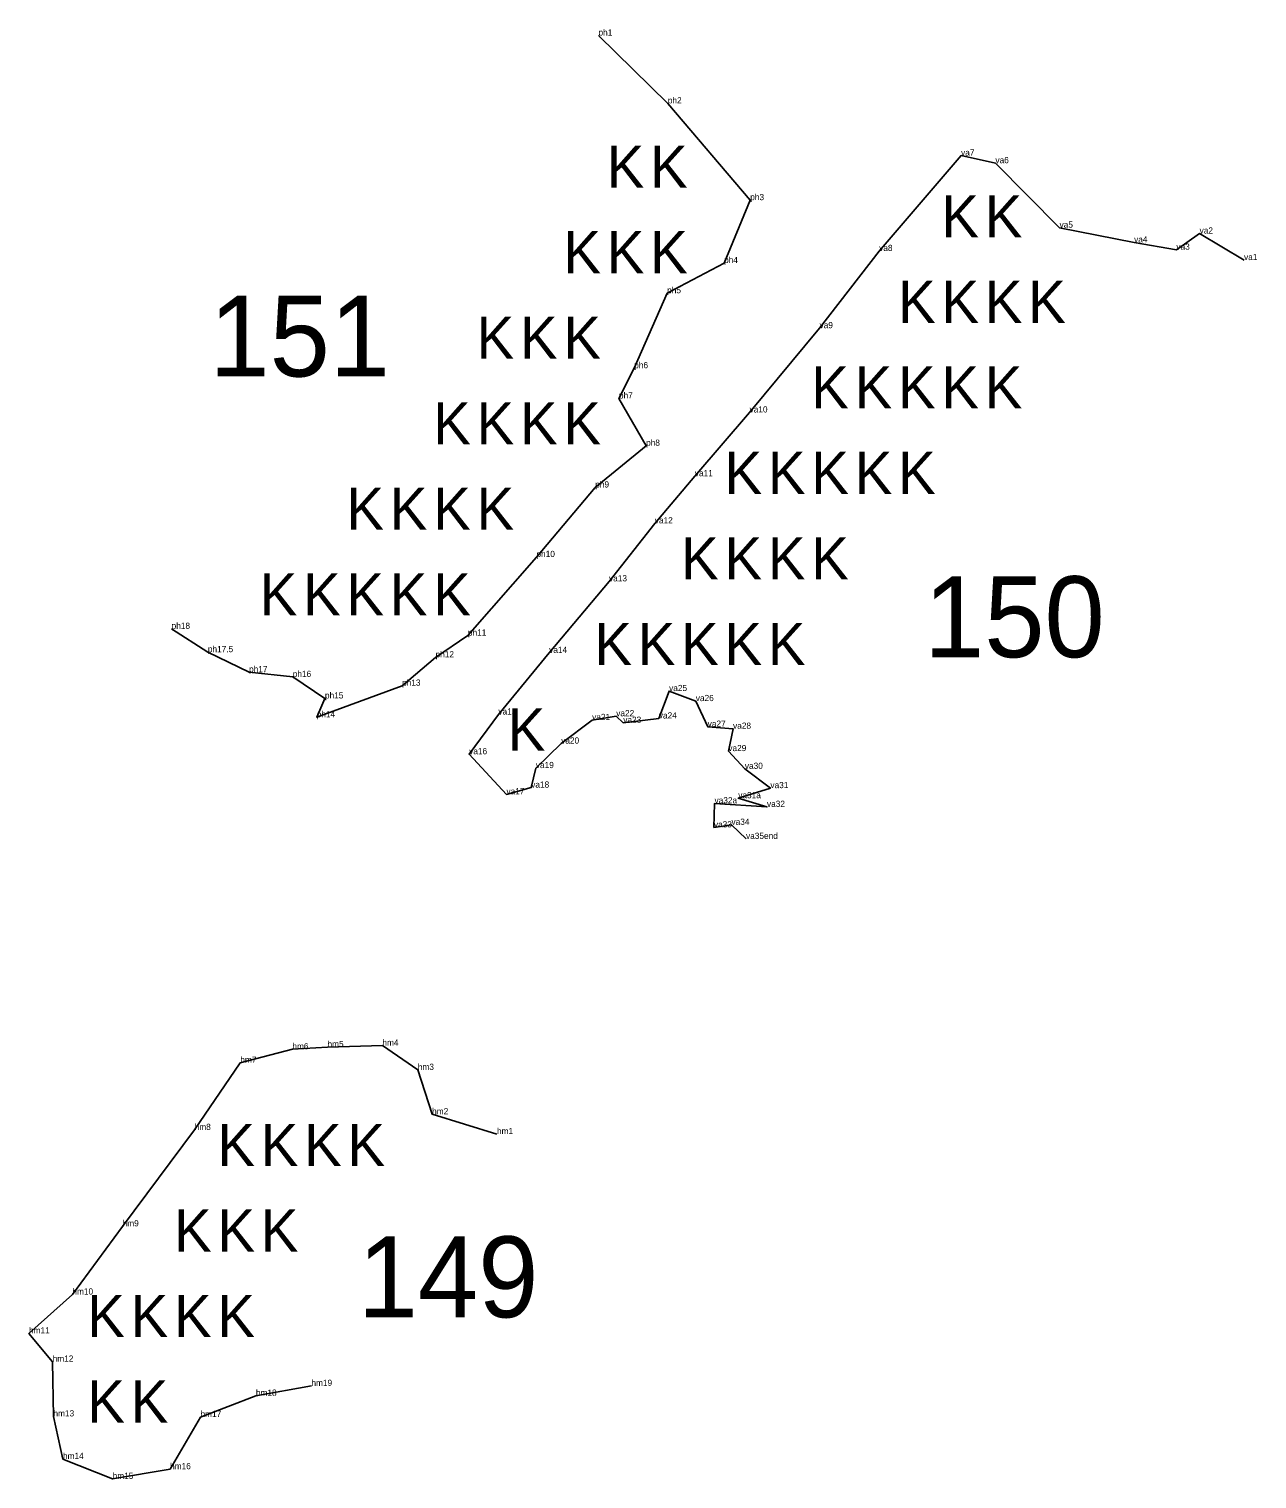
# Model space of a CAD drawing. Extents: x 2072529 to 2268812, y 436423 to 470008.
# Drawn here: x 2173124 to 2174115, y 447172 to 448342 of the extents above; entities that cross this region are included whole.
import ezdxf

# ---------------------------------------------------------------- set-up
doc = ezdxf.new("R2010")
doc.units = 0
for name, color, linetype in [('Old_Level_20', 7, 'Continuous'), ('Old_Level_52', 7, 'Continuous'), ('Old_Level_55', 7, 'Continuous'), ('Old_Level_60', 7, 'Continuous'), ('Old_Level_62', 7, 'Continuous')]:
    doc.layers.add(name, color=color, linetype=linetype)

msp = doc.modelspace()

# ---------------------------------------------------------------- linework, layer by layer
at = {"layer": 'Old_Level_20'}
for p, q in [((2173583.466, 448337), (2173583.466, 448337)), ((2173639.399, 448282.22), (2173639.399, 448282.22)), ((2173876.017, 448240.104), (2173876.017, 448240.104)), ((2173903.753, 448233.99), (2173903.753, 448233.99)), ((2173705.912, 448204.16), (2173705.912, 448204.16)), ((2173955.521, 448181.963), (2173955.521, 448181.963)), ((2174015.642, 448170.074), (2174015.642, 448170.074)), ((2174068.516, 448177.248), (2174068.516, 448177.248)), ((2173809.946, 448163.115), (2173809.946, 448163.115)), ((2174049.767, 448164.155), (2174049.767, 448164.155)), ((2174104.347, 448155.801), (2174104.347, 448155.801)), ((2173684.778, 448153.416), (2173684.778, 448153.416)), ((2173638.87, 448129.059), (2173638.87, 448129.059)), ((2173761.851, 448100.844), (2173761.851, 448100.844)), ((2173612.299, 448068.551), (2173612.299, 448068.551)), ((2173599.96, 448044.129), (2173599.96, 448044.129)), ((2173705.376, 448032.846), (2173705.376, 448032.846)), ((2173621.865, 448005.978), (2173621.865, 448005.978)), ((2173661.232, 447981.429), (2173661.232, 447981.429)), ((2173580.838, 447972.298), (2173580.838, 447972.298)), ((2173628.918, 447943.374), (2173628.918, 447943.374)), ((2173533.431, 447916.219), (2173533.431, 447916.219)), ((2173591.986, 447896.56), (2173591.986, 447896.56)), ((2173239.026, 447858.262), (2173239.026, 447858.262)), ((2173478.1, 447852.84), (2173478.1, 447852.84)), ((2173268.278, 447839.435), (2173268.278, 447839.435)), ((2173543.675, 447838.894), (2173543.675, 447838.894)), ((2173452.001, 447835.245), (2173452.001, 447835.245)), ((2173301.538, 447823.257), (2173301.538, 447823.257)), ((2173336.772, 447819.459), (2173336.772, 447819.459)), ((2173425.014, 447812.384), (2173425.014, 447812.384)), ((2173640.445, 447808.038), (2173640.445, 447808.038)), ((2173362.745, 447802.115), (2173362.745, 447802.115)), ((2173661.975, 447799.96), (2173661.975, 447799.96)), ((2173356.081, 447786.898), (2173356.081, 447786.898)), ((2173502.708, 447789.134), (2173502.708, 447789.134)), ((2173578.339, 447784.692), (2173578.339, 447784.692)), ((2173597.789, 447787.733), (2173597.789, 447787.733)), ((2173603.446, 447782.457), (2173603.446, 447782.457)), ((2173632.137, 447785.936), (2173632.137, 447785.936)), ((2173671.593, 447779.273), (2173671.593, 447779.273)), ((2173692.052, 447777.639), (2173692.052, 447777.639)), ((2173479.117, 447757.064), (2173479.117, 447757.064)), ((2173553.392, 447765.678), (2173553.392, 447765.678)), ((2173688.234, 447759.607), (2173688.234, 447759.607)), ((2173532.95, 447745.903), (2173532.95, 447745.903)), ((2173701.582, 447745.298), (2173701.582, 447745.298)), ((2173509.211, 447724.724), (2173509.211, 447724.724)), ((2173529.203, 447730.149), (2173529.203, 447730.149)), ((2173696.239, 447721.595), (2173696.239, 447721.595)), ((2173722.187, 447729.723), (2173722.187, 447729.723)), ((2173677.109, 447717.448), (2173677.109, 447717.448)), ((2173719.425, 447714.583), (2173719.425, 447714.583)), ((2173690.789, 447700.137), (2173690.789, 447700.137)), ((2173676.612, 447698.048), (2173676.612, 447698.048)), ((2173702.522, 447688.766), (2173702.522, 447688.766)), ((2173336.468, 447518.995), (2173336.468, 447518.995)), ((2173364.809, 447520.816), (2173364.809, 447520.816)), ((2173409.121, 447521.961), (2173409.121, 447521.961)), ((2173294.448, 447508.114), (2173294.448, 447508.114)), ((2173437.702, 447502.381), (2173437.702, 447502.381)), ((2173449.257, 447466.546), (2173449.257, 447466.546)), ((2173257.628, 447453.931), (2173257.628, 447453.931)), ((2173501.562, 447450.544), (2173501.562, 447450.544)), ((2173199.479, 447376.158), (2173199.479, 447376.158)), ((2173158.954, 447321.157), (2173158.954, 447321.157)), ((2173123.958, 447289.75), (2173123.958, 447289.75)), ((2173143.038, 447266.952), (2173143.038, 447266.952)), ((2173351.848, 447247.454), (2173351.848, 447247.454)), ((2173307.042, 447239.465), (2173307.042, 447239.465)), ((2173143.681, 447222.783), (2173143.681, 447222.783)), ((2173262.347, 447222.318), (2173262.347, 447222.318)), ((2173151.353, 447188.418), (2173151.353, 447188.418)), ((2173191.46, 447172.374), (2173191.46, 447172.374)), ((2173237.811, 447180.175), (2173237.811, 447180.175))]:
    msp.add_line(p, q, dxfattribs=at)
at = {"layer": 'Old_Level_52'}
for points in [[(2173583.466, 448337), (2173639.399, 448282.22), (2173705.912, 448204.16), (2173684.778, 448153.416), (2173638.87, 448129.059), (2173612.299, 448068.551), (2173599.96, 448044.129), (2173621.865, 448005.978), (2173580.838, 447972.298), (2173533.431, 447916.219), (2173478.1, 447852.84), (2173452.001, 447835.245), (2173425.014, 447812.384), (2173356.081, 447786.898), (2173362.745, 447802.115), (2173336.772, 447819.459), (2173301.538, 447823.257), (2173268.278, 447839.435), (2173239.026, 447858.262)], [(2173702.522, 447688.766), (2173690.789, 447700.137), (2173676.612, 447698.048), (2173677.109, 447717.448), (2173719.425, 447714.583), (2173696.239, 447721.595), (2173722.187, 447729.723), (2173701.582, 447745.298), (2173688.234, 447759.607), (2173692.052, 447777.639), (2173671.593, 447779.273), (2173661.975, 447799.96), (2173640.445, 447808.038), (2173632.137, 447785.936), (2173603.446, 447782.457), (2173597.789, 447787.733), (2173578.339, 447784.692), (2173553.392, 447765.678), (2173532.95, 447745.903), (2173529.203, 447730.149), (2173509.211, 447724.724), (2173479.117, 447757.064), (2173502.708, 447789.134), (2173543.675, 447838.894), (2173591.986, 447896.56), (2173628.918, 447943.374), (2173661.232, 447981.429), (2173705.376, 448032.846), (2173761.851, 448100.844), (2173809.946, 448163.115), (2173876.017, 448240.104), (2173903.753, 448233.99), (2173955.521, 448181.963), (2174015.642, 448170.074), (2174049.767, 448164.155), (2174068.516, 448177.248), (2174104.347, 448155.801)], [(2173501.562, 447450.544), (2173449.257, 447466.546), (2173437.702, 447502.381), (2173409.121, 447521.961), (2173364.809, 447520.816), (2173336.468, 447518.995), (2173294.448, 447508.114), (2173257.628, 447453.931), (2173199.479, 447376.158), (2173158.954, 447321.157), (2173123.958, 447289.75), (2173143.038, 447266.952), (2173143.681, 447222.783), (2173151.353, 447188.418), (2173191.46, 447172.374), (2173237.811, 447180.175), (2173262.347, 447222.318), (2173307.042, 447239.465), (2173351.848, 447247.454)]]:
    msp.add_lwpolyline(points, dxfattribs=at)

# ---------------------------------------------------------------- texts
at = {"layer": 'Old_Level_55'}
for p in [(2173590.117, 448214.163), (2173625.117, 448214.163), (2173860.167, 448174.1), (2173895.167, 448174.1), (2173555.117, 448145.163), (2173590.117, 448145.163), (2173625.117, 448145.163), (2173825.167, 448105.1), (2173860.167, 448105.1), (2173895.167, 448105.1), (2173930.167, 448105.1), (2173485.117, 448076.163), (2173520.117, 448076.163), (2173555.117, 448076.163), (2173755.167, 448036.1), (2173790.167, 448036.1), (2173825.167, 448036.1), (2173860.167, 448036.1), (2173895.167, 448036.1), (2173450.117, 448007.163), (2173485.117, 448007.163), (2173520.117, 448007.163), (2173555.117, 448007.163), (2173685.167, 447967.1), (2173720.167, 447967.1), (2173755.167, 447967.1), (2173790.167, 447967.1), (2173825.167, 447967.1), (2173380.117, 447938.163), (2173415.117, 447938.163), (2173450.117, 447938.163), (2173485.117, 447938.163), (2173650.167, 447898.1), (2173685.167, 447898.1), (2173720.167, 447898.1), (2173755.167, 447898.1), (2173310.117, 447869.163), (2173345.117, 447869.163), (2173380.117, 447869.163), (2173415.117, 447869.163), (2173450.117, 447869.163), (2173580.167, 447829.1), (2173615.167, 447829.1), (2173650.167, 447829.1), (2173685.167, 447829.1), (2173720.167, 447829.1), (2173510.167, 447760.1), (2173275.966, 447424.812), (2173310.966, 447424.812), (2173345.966, 447424.812), (2173380.966, 447424.812), (2173240.966, 447355.812), (2173275.966, 447355.812), (2173310.966, 447355.812), (2173170.966, 447286.812), (2173205.966, 447286.812), (2173240.966, 447286.812), (2173275.966, 447286.812), (2173170.966, 447217.812), (2173205.966, 447217.812)]:
    msp.add_text('K', height=34, dxfattribs=at).set_placement(p)
at = {"layer": 'Old_Level_60'}
for s, p in [('ph1', (2173583.466, 448337)), ('ph2', (2173639.399, 448282.22)), ('va7', (2173876.017, 448240.104)), ('va6', (2173903.753, 448233.99)), ('ph3', (2173705.912, 448204.16)), ('va5', (2173955.521, 448181.963)), ('va2', (2174068.516, 448177.248)), ('va8', (2173809.946, 448163.115)), ('va4', (2174015.642, 448170.074)), ('va3', (2174049.767, 448164.155)), ('ph4', (2173684.778, 448153.416)), ('va1', (2174104.347, 448155.801)), ('ph5', (2173638.87, 448129.059)), ('va9', (2173761.851, 448100.844)), ('ph6', (2173612.299, 448068.551)), ('ph7', (2173599.96, 448044.129)), ('va10', (2173705.376, 448032.846)), ('ph8', (2173621.865, 448005.978)), ('va11', (2173661.232, 447981.429)), ('ph9', (2173580.838, 447972.298)), ('va12', (2173628.918, 447943.374)), ('ph10', (2173533.431, 447916.219)), ('va13', (2173591.986, 447896.56)), ('ph18', (2173239.026, 447858.262)), ('ph11', (2173478.1, 447852.84)), ('ph17.5', (2173268.278, 447839.435)), ('ph12', (2173452.001, 447835.245)), ('va14', (2173543.675, 447838.894)), ('ph17', (2173301.538, 447823.257)), ('ph16', (2173336.772, 447819.459)), ('ph13', (2173425.014, 447812.384)), ('ph15', (2173362.745, 447802.115)), ('va25', (2173640.445, 447808.038)), ('va26', (2173661.975, 447799.96)), ('ph14', (2173356.081, 447786.898)), ('va15', (2173502.708, 447789.134)), ('va22', (2173597.789, 447787.733)), ('va21', (2173578.339, 447784.692)), ('va23', (2173603.446, 447782.457)), ('va24', (2173632.137, 447785.936)), ('va27', (2173671.593, 447779.273)), ('va28', (2173692.052, 447777.639)), ('va20', (2173553.392, 447765.678)), ('va16', (2173479.117, 447757.064)), ('va29', (2173688.234, 447759.607)), ('va19', (2173532.95, 447745.903)), ('va30', (2173701.582, 447745.298)), ('va18', (2173529.203, 447730.149)), ('va31', (2173722.187, 447729.723)), ('va17', (2173509.211, 447724.724)), ('va32a', (2173677.109, 447717.448)), ('va31a', (2173696.239, 447721.595)), ('va32', (2173719.425, 447714.583)), ('va33', (2173676.612, 447698.048)), ('va34', (2173690.789, 447700.137)), ('va35end', (2173702.522, 447688.766)), ('hm6', (2173336.468, 447518.995)), ('hm5', (2173364.809, 447520.816)), ('hm4', (2173409.121, 447521.961)), ('hm7', (2173294.448, 447508.114)), ('hm3', (2173437.702, 447502.381)), ('hm2', (2173449.257, 447466.546)), ('hm8', (2173257.628, 447453.931)), ('hm1', (2173501.562, 447450.544)), ('hm9', (2173199.479, 447376.158)), ('hm10', (2173158.954, 447321.157)), ('hm11', (2173123.958, 447289.75)), ('hm12', (2173143.038, 447266.952)), ('hm18', (2173307.042, 447239.465)), ('hm19', (2173351.848, 447247.454)), ('hm13', (2173143.681, 447222.783)), ('hm17', (2173262.347, 447222.318)), ('hm14', (2173151.353, 447188.418)), ('hm16', (2173237.811, 447180.175)), ('hm15', (2173191.46, 447172.374))]:
    msp.add_text(s, height=5, dxfattribs=at).set_placement(p)
at = {"layer": 'Old_Level_62'}
for s, p in [('151', (2173269.526, 448061.88)), ('150', (2173846.172, 447835.346)), ('149', (2173389.238, 447302.718))]:
    msp.add_text(s, height=65.34, dxfattribs=at).set_placement(p)

doc.saveas('drawing.dxf')
